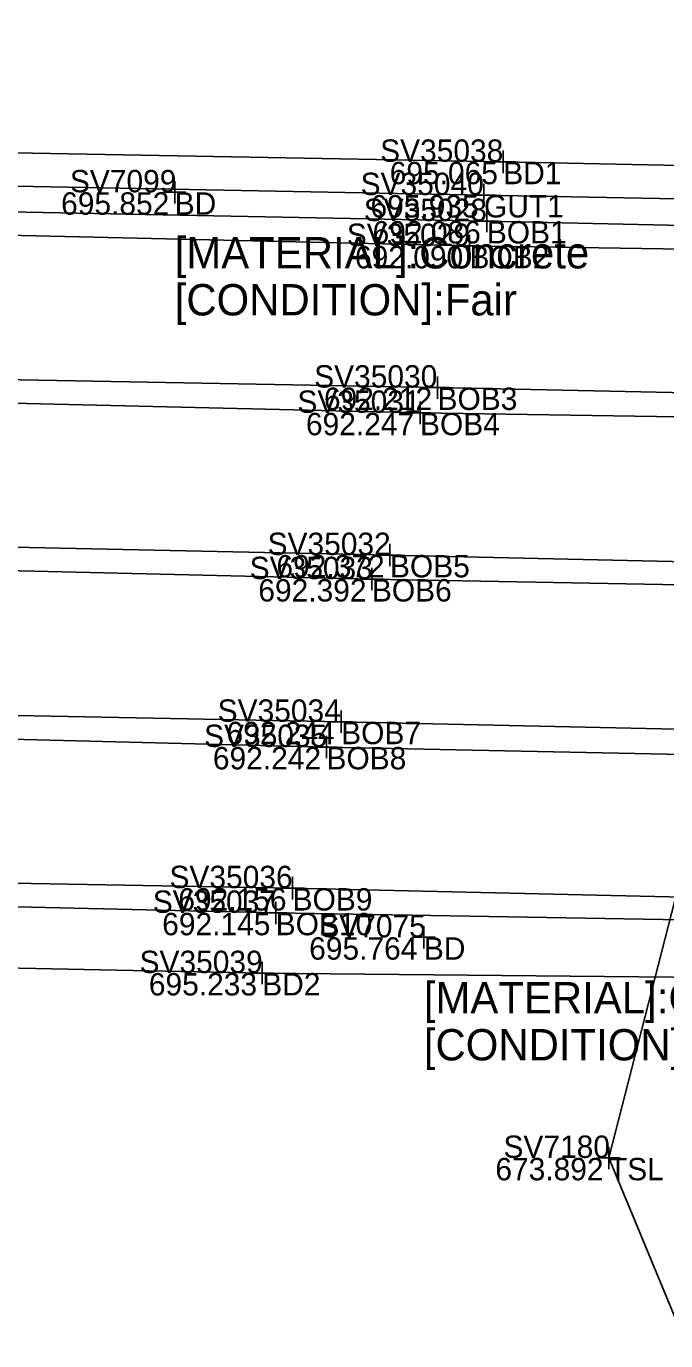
# Model space of a CAD drawing. Extents: x 1660019 to 1662995, y 619975 to 620342.
# Drawn here: x 1661451.1 to 1661479.7, y 620194.9 to 620253.7 of the extents above; entities that cross this region are included whole.
import ezdxf

# ---------------------------------------------------------------- set-up
doc = ezdxf.new("R2010")
doc.units = 0
for name, color, linetype in [('BR_X_Rail_Object', 7, 'Continuous'), ('BR_X_SV_Bottom_of_Beam', 7, 'Continuous'), ('BR_X_SV_Bottom_of_Beam_Text', 7, 'Continuous'), ('BR_X_SV_Deck_Top', 7, 'Continuous'), ('BR_X_SV_Deck_Top_Text', 7, 'Continuous'), ('PV_X_Curb', 7, 'Continuous'), ('RD_P_GR_Lt', 7, 'Continuous'), ('RD_X_GR_Bar', 7, 'Continuous'), ('RD_X_Wall', 7, 'Continuous'), ('SV_X_Text', 7, 'Continuous'), ('SV_X_Toe_of_Slope', 7, 'Continuous')]:
    doc.layers.add(name, color=color, linetype=linetype)

msp = doc.modelspace()

# ---------------------------------------------------------------- linework, layer by layer
at = {"layer": 'BR_X_SV_Bottom_of_Beam'}
for points in [[(1661523.404, 620243.849), (1661497.415, 620244.383), (1661471.694, 620244.95), (1661445.773, 620245.45), (1661419.903, 620245.974), (1661394.009, 620246.51), (1661368.147, 620247.032), (1661342.287, 620247.488), (1661316.311, 620248.045), (1661290.557, 620248.602), (1661264.648, 620249.031), (1661238.6, 620249.579)], [(1661517.582, 620243.008), (1661496.897, 620243.44), (1661470.919, 620243.838), (1661445.09, 620244.441), (1661419.147, 620244.946), (1661393.26, 620245.417), (1661367.358, 620245.921), (1661341.629, 620246.518), (1661315.646, 620247.115), (1661289.746, 620247.518), (1661264.383, 620248.322), (1661238.204, 620248.614)], [(1661521.265, 620236.365), (1661495.332, 620236.959), (1661469.491, 620237.512), (1661443.572, 620237.996), (1661417.708, 620238.508), (1661391.884, 620239.08), (1661365.994, 620239.561), (1661340.119, 620240.034), (1661314.197, 620240.589), (1661288.354, 620241.145), (1661262.476, 620241.611), (1661236.623, 620242.15)], [(1661520.605, 620235.452), (1661494.63, 620235.975), (1661468.71, 620236.383), (1661442.944, 620236.996), (1661417.103, 620237.514), (1661391.103, 620237.982), (1661365.202, 620238.448), (1661339.374, 620239.07), (1661313.502, 620239.591), (1661287.59, 620239.99), (1661261.723, 620240.632), (1661235.908, 620241.144)], [(1661519.081, 620228.953), (1661493.234, 620229.438), (1661467.368, 620230.031), (1661441.422, 620230.57), (1661415.6, 620231.071), (1661389.731, 620231.651), (1661363.823, 620232.132), (1661337.817, 620232.613), (1661311.988, 620233.076), (1661286.183, 620233.721), (1661260.328, 620234.129), (1661234.382, 620234.656)], [(1661518.51, 620227.977), (1661492.527, 620228.475), (1661466.56, 620228.954), (1661440.742, 620229.56), (1661414.823, 620230.069), (1661388.938, 620230.522), (1661363.07, 620231.021), (1661337.298, 620231.612), (1661311.527, 620232.162), (1661285.446, 620232.587), (1661259.588, 620233.138), (1661233.669, 620233.674)], [(1661516.938, 620221.488), (1661491.079, 620222.019), (1661465.187, 620222.58), (1661439.251, 620223.092), (1661413.441, 620223.61), (1661387.584, 620224.174), (1661361.703, 620224.657), (1661335.742, 620225.126), (1661309.876, 620225.693), (1661284.015, 620226.238), (1661258.155, 620226.696), (1661232.1, 620227.235)], [(1661516.255, 620220.542), (1661490.624, 620220.907), (1661464.53, 620221.454), (1661438.64, 620222.101), (1661412.707, 620222.613), (1661386.76, 620223.066), (1661360.949, 620223.557), (1661335.05, 620224.176), (1661309.206, 620224.717), (1661283.267, 620225.126), (1661257.537, 620225.694), (1661231.605, 620226.262)], [(1661514.756, 620214.059), (1661488.914, 620214.555), (1661463.017, 620215.148), (1661437.126, 620215.616), (1661411.256, 620216.167), (1661385.428, 620216.691), (1661359.541, 620217.184), (1661333.602, 620217.682), (1661307.754, 620218.183), (1661281.891, 620218.773), (1661255.858, 620219.275), (1661229.67, 620219.799)], [(1661514.073, 620213.08), (1661488.21, 620213.597), (1661462.263, 620214.044), (1661436.515, 620214.643), (1661410.516, 620215.165), (1661384.602, 620215.601), (1661358.815, 620216.084), (1661332.968, 620216.701), (1661307.113, 620217.251), (1661281.101, 620217.691), (1661255.319, 620218.266), (1661229.464, 620218.851)]]:
    msp.add_lwpolyline(points, dxfattribs=at)
at = {"layer": 'BR_X_SV_Deck_Top'}
for points in [[(1661524.154, 620246.519), (1661498.291, 620247.067), (1661472.426, 620247.598), (1661446.524, 620248.074), (1661420.55, 620248.604), (1661394.772, 620249.021), (1661368.927, 620249.743), (1661342.743, 620250.117), (1661316.866, 620250.706), (1661291.246, 620251.013), (1661265.132, 620251.796)], [(1661513.529, 620210.295), (1661487.664, 620211.099), (1661461.66, 620211.354), (1661435.632, 620211.885), (1661409.962, 620212.424), (1661383.838, 620212.928), (1661332.298, 620213.947), (1661306.248, 620214.439), (1661280.429, 620214.969), (1661254.732, 620215.771)]]:
    msp.add_lwpolyline(points, dxfattribs=at)
at = {"layer": 'PV_X_Curb'}
msp.add_lwpolyline([(1661523.342, 620245.121), (1661471.566, 620246.113), (1661445.996, 620246.597), (1661316.22, 620249.01), (1661290.79, 620249.439), (1661264.952, 620250.247), (1661238.714, 620250.79)], dxfattribs=at)
at = {"layer": 'RD_P_GR_Lt'}
for p, q in [((1661472.426, 620248.098), (1661472.426, 620247.098)), ((1661471.926, 620247.598), (1661472.926, 620247.598)), ((1661472.426, 620247.598), (1661472.426, 620247.598)), ((1661457.75, 620246.736), (1661457.75, 620245.736)), ((1661471.566, 620246.613), (1661471.566, 620245.613)), ((1661457.25, 620246.236), (1661458.25, 620246.236)), ((1661457.75, 620246.236), (1661457.75, 620246.236)), ((1661471.066, 620246.113), (1661472.066, 620246.113)), ((1661471.566, 620246.113), (1661471.566, 620246.113)), ((1661471.694, 620245.45), (1661471.694, 620244.45)), ((1661471.194, 620244.95), (1661472.194, 620244.95)), ((1661471.694, 620244.95), (1661471.694, 620244.95)), ((1661470.919, 620244.338), (1661470.919, 620243.338)), ((1661470.419, 620243.838), (1661471.419, 620243.838)), ((1661470.919, 620243.838), (1661470.919, 620243.838)), ((1661469.491, 620238.012), (1661469.491, 620237.012)), ((1661468.991, 620237.512), (1661469.991, 620237.512)), ((1661469.491, 620237.512), (1661469.491, 620237.512)), ((1661468.71, 620236.883), (1661468.71, 620235.883)), ((1661468.21, 620236.383), (1661469.21, 620236.383)), ((1661468.71, 620236.383), (1661468.71, 620236.383)), ((1661467.368, 620230.531), (1661467.368, 620229.531)), ((1661466.868, 620230.031), (1661467.868, 620230.031)), ((1661467.368, 620230.031), (1661467.368, 620230.031)), ((1661466.56, 620229.454), (1661466.56, 620228.454)), ((1661466.06, 620228.954), (1661467.06, 620228.954)), ((1661466.56, 620228.954), (1661466.56, 620228.954)), ((1661464.687, 620222.58), (1661465.687, 620222.58)), ((1661465.187, 620223.08), (1661465.187, 620222.08)), ((1661465.187, 620222.58), (1661465.187, 620222.58)), ((1661464.53, 620221.954), (1661464.53, 620220.954)), ((1661464.03, 620221.454), (1661465.03, 620221.454)), ((1661464.53, 620221.454), (1661464.53, 620221.454)), ((1661463.017, 620215.648), (1661463.017, 620214.648)), ((1661462.517, 620215.148), (1661463.517, 620215.148)), ((1661463.017, 620215.148), (1661463.017, 620215.148)), ((1661462.263, 620214.544), (1661462.263, 620213.544)), ((1661461.763, 620214.044), (1661462.763, 620214.044)), ((1661462.263, 620214.044), (1661462.263, 620214.044)), ((1661468.881, 620213.452), (1661468.881, 620212.452)), ((1661468.381, 620212.952), (1661469.381, 620212.952)), ((1661468.881, 620212.952), (1661468.881, 620212.952)), ((1661461.16, 620211.354), (1661462.16, 620211.354)), ((1661461.66, 620211.854), (1661461.66, 620210.854)), ((1661461.66, 620211.354), (1661461.66, 620211.354)), ((1661477.149, 620203.596), (1661477.149, 620202.596)), ((1661476.649, 620203.096), (1661477.649, 620203.096)), ((1661477.149, 620203.096), (1661477.149, 620203.096))]:
    msp.add_line(p, q, dxfattribs=at)
at = {"layer": 'SV_X_Toe_of_Slope'}
msp.add_lwpolyline([(1661490.605, 620170.614), (1661477.149, 620203.096), (1661498.786, 620287.484), (1661510.242, 620298.378), (1661539.687, 620302.32)], dxfattribs=at)

# ---------------------------------------------------------------- texts
at = {"layer": 'BR_X_Rail_Object'}
for s, p in [('GUT1', (1661471.566, 620245.113)), ('TSL', (1661477.149, 620202.096))]:
    msp.add_text(s, height=1, dxfattribs=at).set_placement(p)
at = {"layer": 'BR_X_SV_Bottom_of_Beam_Text'}
for s, p in [('SV35028', (1661466.197, 620244.95)), ('SV35029', (1661465.439, 620243.838)), ('692.086', (1661466.59, 620243.95)), ('BOB1', (1661471.694, 620243.95)), ('692.090', (1661465.805, 620242.838)), ('BOB2', (1661470.919, 620242.838)), ('SV35030', (1661463.981, 620237.512)), ('SV35031', (1661463.232, 620236.383)), ('692.212', (1661464.418, 620236.512)), ('BOB3', (1661469.491, 620236.512)), ('692.247', (1661463.614, 620235.383)), ('BOB4', (1661468.71, 620235.383)), ('SV35032', (1661461.899, 620230.031)), ('SV35033', (1661461.1, 620228.954)), ('692.372', (1661462.295, 620229.031)), ('BOB5', (1661467.368, 620229.031)), ('692.392', (1661461.487, 620227.954)), ('BOB6', (1661466.56, 620227.954)), ('SV35034', (1661459.669, 620222.58)), ('692.244', (1661460.065, 620221.58)), ('BOB7', (1661465.187, 620221.58)), ('SV35035', (1661459.063, 620221.454)), ('692.242', (1661459.457, 620220.454)), ('BOB8', (1661464.53, 620220.454)), ('SV35036', (1661457.517, 620215.148)), ('SV35037', (1661456.771, 620214.044)), ('692.156', (1661457.913, 620214.148)), ('BOB9', (1661463.017, 620214.148)), ('692.145', (1661457.193, 620213.044)), ('BOB10', (1661462.263, 620213.044))]:
    msp.add_text(s, height=1, dxfattribs=at).set_placement(p)
at = {"layer": 'BR_X_SV_Deck_Top_Text'}
for s, p in [('SV35038', (1661466.929, 620247.598)), ('SV7099', (1661453.068, 620246.236)), ('695.065', (1661467.356, 620246.598)), ('BD1', (1661472.426, 620246.598)), ('695.852', (1661452.677, 620245.236)), ('BD', (1661457.75, 620245.236)), ('SV7075', (1661464.212, 620212.952)), ('695.764', (1661463.759, 620211.952)), ('BD', (1661468.881, 620211.952)), ('SV35039', (1661456.18, 620211.354)), ('695.233', (1661456.596, 620210.354)), ('BD2', (1661461.66, 620210.354))]:
    msp.add_text(s, height=1, dxfattribs=at).set_placement(p)
at = {"layer": 'RD_X_GR_Bar'}
for s, p in [('695.935', (1661466.496, 620245.113)), ('673.892', (1661472.076, 620202.096))]:
    msp.add_text(s, height=1, dxfattribs=at).set_placement(p)
at = {"layer": 'RD_X_Wall'}
for s, p in [('SV35040', (1661466.056, 620246.113)), ('SV7180', (1661472.437, 620203.096))]:
    msp.add_text(s, height=1, dxfattribs=at).set_placement(p)
at = {"layer": 'SV_X_Text'}
for s, p in [('[MATERIAL]:Concrete', (1661457.75, 620242.836)), ('[CONDITION]:Fair', (1661457.75, 620240.736)), ('[MATERIAL]:Concrete', (1661468.881, 620209.552)), ('[CONDITION]:Fair', (1661468.881, 620207.452))]:
    msp.add_text(s, height=1.4, dxfattribs=at).set_placement(p)

doc.saveas('drawing.dxf')
